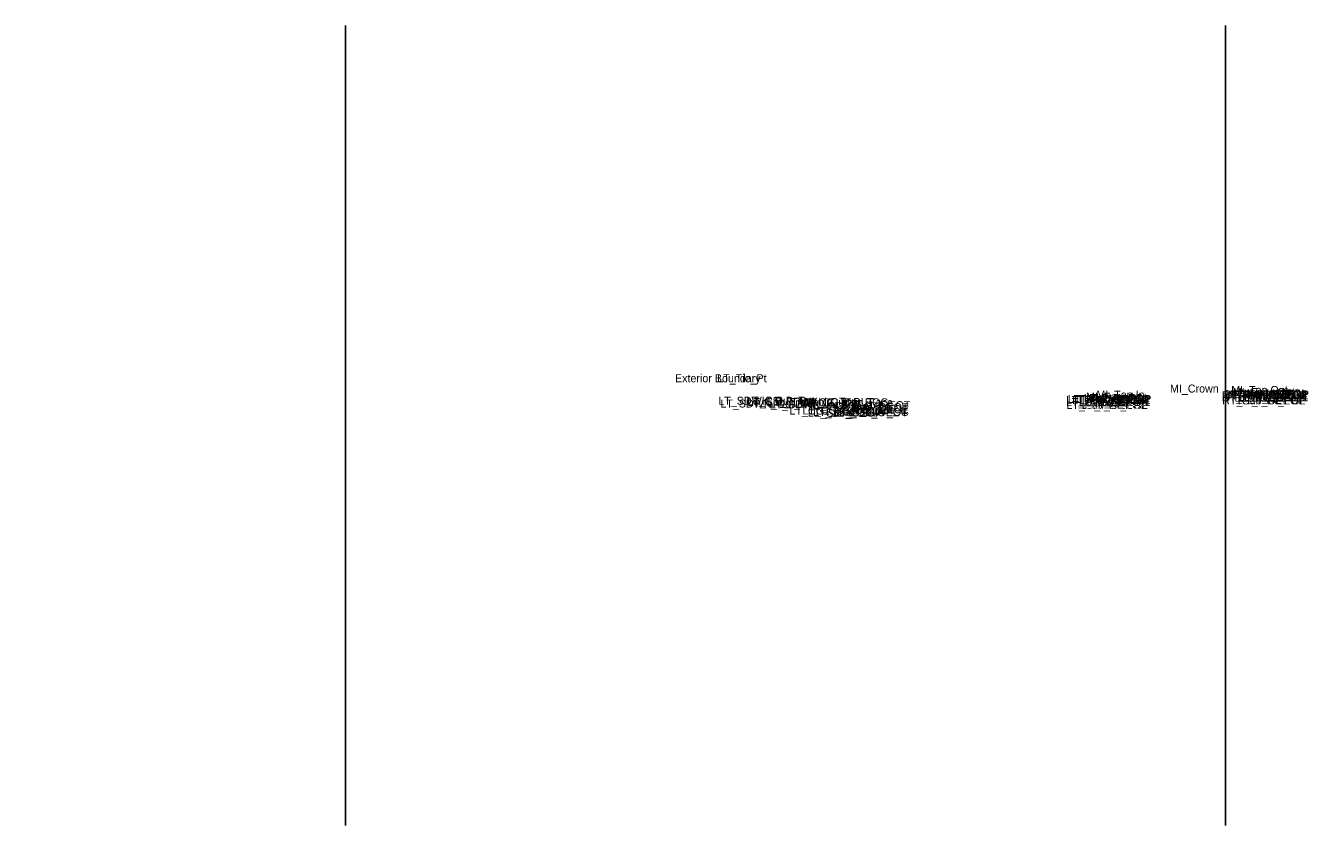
# Model space of a CAD drawing. Extents: x 0 to 6300, y -50 to 9550.
# Drawn here: x 3000 to 3160.3, y 450 to 550 of the extents above; entities that cross this region are included whole.
import ezdxf

# ---------------------------------------------------------------- set-up
doc = ezdxf.new("R2010")
doc.units = 0
for name, color, linetype in [('Default', 7, 'Continuous'), ('Prop XS Exc Vertical Line 1', 7, 'Continuous'), ('Prop XS Exc Vertical Line 2', 7, 'Continuous')]:
    doc.layers.add(name, color=color, linetype=linetype)

msp = doc.modelspace()

# ---------------------------------------------------------------- linework, layer by layer
at = {"layer": 'Prop XS Exc Vertical Line 1'}
msp.add_line((3040, 550), (3040, 450), dxfattribs=at)
at = {"layer": 'Prop XS Exc Vertical Line 2'}
msp.add_line((3150, 550), (3150, 450), dxfattribs=at)

# ---------------------------------------------------------------- texts
at = {"layer": 'Default'}
for s, height, p in [('Exterior Boundary', 1, (3081.17, 505.41)), ('LT_Tie_Pt', 1, (3086.45, 505.41)), ('MI_Crown', 1, (3143.04, 504.12)), ('LT_SDWK_Out_Top', 1, (3086.58, 502.59)), ('LT_CSLP_Pnt', 1, (3090.1, 502.59)), ('LT_Sub_Trench_Out_DLT', 1, (3090.21, 502.44)), ('LT_SDWK_In_Top', 1, (3092.74, 502.49)), ('LT_PV2_OEEOP', 1, (3130.04, 502.68)), ('LT_PV1_OEEOP', 1, (3130.27, 502.81)), ('LT_PV2_IEEOP', 1, (3130.8, 502.68)), ('LT_PV1_IEEOP', 1, (3131.04, 502.81)), ('LT_PV2_PGL1', 1, (3131.63, 502.68)), ('LT_PV2_PGL', 1, (3132.01, 502.68)), ('LT_PV1_PGL', 1, (3132.25, 502.93)), ('MI_Face In', 1, (3132.55, 503.1)), ('MI_Bot In', 1, (3133.72, 502.93)), ('MI_Top In', 1, (3133.84, 503.35)), ('RT_PV2_OEEOP', 1, (3149.52, 503.27)), ('RT_PV3_OEEOP', 1, (3149.52, 503.02)), ('RT_Sub_OEEOP', 1, (3149.57, 502.64)), ('RT_PV1_OEEOP', 1, (3149.76, 503.39)), ('RT_PV2_IEEOP', 1, (3150.28, 503.27)), ('RT_PV1_IEEOP', 1, (3150.52, 503.39)), ('MI_Top Out', 1, (3150.7, 503.94)), ('MI_Face Out', 1, (3150.91, 503.69)), ('RT_PV2_PGL1', 1, (3151.12, 503.27)), ('RT_PV3_PGL1', 1, (3151.12, 503.02)), ('RT_PV2_PGL', 1, (3151.5, 503.27)), ('RT_PV4_PGL', 1, (3151.5, 502.64)), ('RT_PV1_PGL', 1, (3151.74, 503.52)), ('MI_Bot Out', 1, (3152.1, 503.52)), ('LT_SDWK_Out_Bot', 1, (3086.83, 502.25)), ('LT_SDWK_In_Bot', 1, (3092.99, 502.15)), ('LT_CG1_Shelf_Out', 1, (3095.48, 501.36)), ('LT_CG_Top_BOC', 1, (3096.81, 502.4)), ('LT_CG_Bot_BOC', 1, (3097.09, 501.38)), ('LT_CG_Top_Face', 1, (3097.34, 502.4)), ('LT_Sub_OEOP', 1, (3097.77, 501.11)), ('LT_CG_Top_Gut', 1, (3097.87, 501.9)), ('LT_Sub_OEOT_CG', 1, (3098.44, 501.2)), ('LT_PV2_OEOT', 1, (3100.99, 501.79)), ('LT_PV3_OEOT', 1, (3100.99, 501.54)), ('LT_Sub_OEOT', 1, (3101.04, 501.16)), ('LT_PV1_OEOT', 1, (3101.23, 502.04)), ('LT_CG_Bot_IE', 1, (3101.34, 501.45)), ('LT_PV3_OEEOP', 1, (3130.04, 502.43)), ('LT_Sub_OEEOP', 1, (3130.08, 502.06)), ('LT_PV3_PGL1', 1, (3131.63, 502.43)), ('LT_PV4_PGL', 1, (3132.01, 502.06)), ('-', 0.0001, (3000, 500))]:
    msp.add_text(s, height=height, dxfattribs=at).set_placement(p)

doc.saveas('drawing.dxf')
